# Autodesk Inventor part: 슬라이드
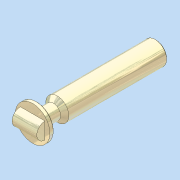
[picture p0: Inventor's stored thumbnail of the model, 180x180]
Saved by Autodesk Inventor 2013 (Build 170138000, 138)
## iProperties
Company: 한국ATC센터
Created: 2014-10
Part Number: 슬라이드
Document SubType Name: Modeling
Designer: 한국ATC센터
Density: 7.86 g/cm^3
Material: 강, 연강
Mass: 728.405 g
Surface Area: 164.68 cm^2
Volume: 92.6724 cm^3
Author: KYOUNG IL JANG
Revision Number: 1
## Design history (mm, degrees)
sketch "스케치1"
  geometry: L1 (-14, 195)-(-14, 171) reference; L2 (19, 106.5)-(-19, 106.5) reference; L3 (0, 106.5)-(0, 256.5); L4 (0, 256.5)-(-14, 256.5); L5 (-14, 256.5)-(-14, 136.5); L6 (-14, 111.5)-(-21, 111.5); L7 (-21, 111.5)-(-21, 106.5); L8 (-21, 106.5)-(0, 106.5); L9 (-14, 111.5)-(-9, 111.5); L10 (-9, 111.5)-(-9, 131.5); L11 (-9, 131.5)-(-14, 136.5); L12 (-14, 136.5)-(-14, 111.5); 1 further point
  constraints: 24 end point, 5 perpendicular, 3 parallel, 1 collinear, 1 horizontal, 1 midpoint, 1 point on line, 1 vertical, 4 other
  dimensions: "d0" = 5 distance between parallel lines of L6 L8; "d1" = 42 diameter of L7 L3; "d2" = 150 distance of L3.start L3.end; "d3" = 135 deg angle of L11 L5; "d4" = 18 diameter of L10 L3; "d5" = 30 distance from line of L5.end L8
revolve "회전1" sketch "스케치1" stored, may be unused: angle "d6" = 90 deg
chamfer "모따기1" distance "d7" = 1; stored, may be unused: second distance "d8" = 2, angle "d9" = 45 deg
fillet "모깎기1" dims "d10" = 2
sketch "스케치2"
  geometry: L1 (21, 106.5)-(-21, 106.5) reference; L2 (-15, 96.5)-(15, 96.5); L3 (15, 96.5)-(15, 106.5); L4 (15, 106.5)-(-15, 106.5); L5 (-15, 106.5)-(-15, 96.5); 2 further points
  constraints: 8 end point, 2 midpoint, 2 parallel, 1 horizontal, 1 perpendicular, 1 point on line
  dimensions: "d11" = 20 diameter of L2 L4; "d12" = 30 distance between parallel lines of L3 L5
revolve "회전2" sketch "스케치2" stored, may be unused: angle "d13" = 180 deg
node "솔리드1"
